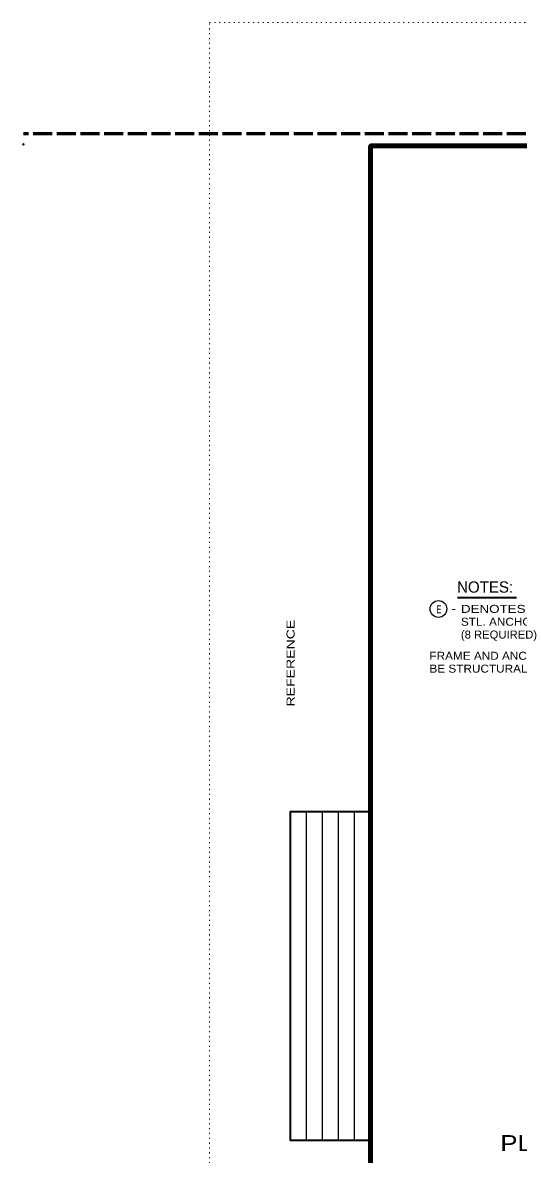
# Model space of a CAD drawing. Extents: x 312583 to 312854, y 144419 to 144597.
# Drawn here: x 312583.5 to 312630.5, y 144489.3 to 144596.8 of the extents above; entities that cross this region are included whole.
import ezdxf
from ezdxf.enums import TextEntityAlignment as Align

# ---------------------------------------------------------------- set-up
doc = ezdxf.new("R2010")
doc.units = 0
doc.header["$LTSCALE"] = 0.3
doc.header["$PDMODE"] = 32
doc.header["$PDSIZE"] = 0.15
doc.linetypes.add('DOTTED', pattern=[1.5, 0.3, -1.2])
doc.linetypes.add('LONG_DASHED', pattern=[7.5, 6, -1.5])
doc.layers.add('1', color=7, linetype='Continuous', lineweight=13)
doc.layers.add('63', color=7, linetype='DOTTED', lineweight=13)

msp = doc.modelspace()

# ---------------------------------------------------------------- linework, layer by layer
at = {"layer": '1', "linetype": 'DOTTED'}
msp.add_line((312601.2, 144418.5846), (312601.2, 144596.7846), dxfattribs=at)
at = {"layer": '1', "linetype": 'LONG_DASHED', "lineweight": 60}
msp.add_line((312851.75, 144586.2246), (312583.526, 144586.2246), dxfattribs=at)
at = {"layer": '1', "lineweight": 35}
msp.add_line((312624.7486, 144542.2003), (312630.3683, 144542.2003), dxfattribs=at)
at = {"layer": '1'}
msp.add_line((312624.2503, 144541.0503), (312624.5186, 144541.0503), dxfattribs=at)
at = {"layer": '1', "lineweight": 25}
for p, q in [((312610.4087, 144490.6573), (312610.4087, 144521.8756)), ((312611.9315, 144490.6573), (312611.9315, 144521.8756)), ((312613.4543, 144490.6573), (312613.4543, 144521.8756)), ((312614.9772, 144490.6573), (312614.9772, 144521.8756))]:
    msp.add_line(p, q, dxfattribs=at)
at = {"layer": '1', "lineweight": 158}
msp.add_lwpolyline([(312616.5, 144423.1446), (312616.5, 144585.0846), (312849, 144585.0846)], dxfattribs=at)
at = {"layer": '1', "lineweight": 35}
msp.add_lwpolyline([(312616.5, 144490.6573), (312608.8858, 144490.6573), (312608.8858, 144521.8756), (312616.5, 144521.8756)], dxfattribs=at)
at = {"layer": '1', "lineweight": 25}
msp.add_circle((312622.9421, 144541.1145), 0.7964, dxfattribs=at)
at = {"layer": '1'}
msp.add_point((312583.526, 144585.2246), dxfattribs=at)
at = {"layer": '63'}
msp.add_line((312601.2, 144596.7846), (312853.5, 144596.7846), dxfattribs=at)

# ---------------------------------------------------------------- texts
at = {"layer": '1'}
msp.add_text('NOTES:', height=1.07, dxfattribs=at).set_placement((312627.3775, 144542.6629), align=Align.CENTER)
for s, width, p in [('DENOTES 30 BY 6 BY 200 MM', 1.25, (312625.0783, 144540.7426)), ('E', 0.7, (312622.7544, 144540.6957)), ('STL. ANCHORS', 1.1, (312625.0783, 144539.5226)), ('(8 REQUIRED)', 1.05, (312625.0783, 144538.3026)), ('FRAME AND ANCHORS SHALL', 1.1, (312622.0883, 144536.2883)), ('BE STRUCTURAL STEEL', 1.1, (312622.0883, 144535.0683))]:
    msp.add_text(s, height=0.76, dxfattribs=dict(at, width=width)).set_placement(p)
at = {"layer": '1', "width": 1.3}
msp.add_text('REFERENCE                                                              ', height=0.7682, rotation=90, dxfattribs=at).set_placement((312609.2854, 144531.8549))
at = {"layer": '1', "width": 1.2}
msp.add_text('PLAN-FRAME AND COVER FOR 250 BY 900 MM JUNCTION BOX', height=1.52, dxfattribs=at).set_placement((312665.6882, 144489.6359), align=Align.CENTER)

doc.saveas('drawing.dxf')
